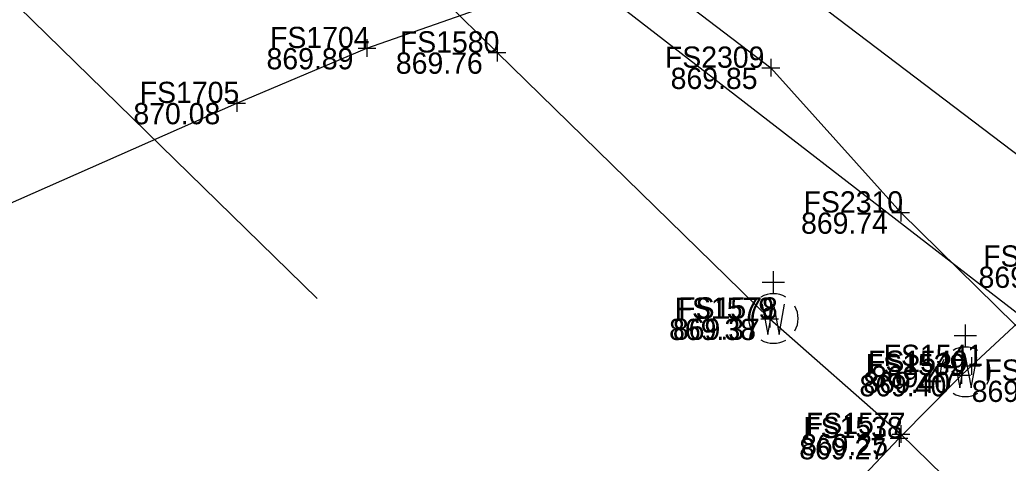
# Model space of a CAD drawing. Extents: x 1479420 to 1479833, y 379731 to 380103.
# Drawn here: x 1479633 to 1479688.8, y 379912.2 to 379937.2 of the extents above; entities that cross this region are included whole.
import ezdxf

# ---------------------------------------------------------------- set-up
doc = ezdxf.new("R2010")
doc.units = 0
for name, color, linetype in [('PM_X_CL_Double_Solid', 7, 'Continuous'), ('PM_X_Crosswalk', 7, 'Continuous'), ('SV_X_Shot_Marker', 7, 'Continuous'), ('SV_X_Text_Elevation', 7, 'Continuous'), ('SV_X_Text_Name', 7, 'Continuous'), ('UT_X_Gas', 7, 'Continuous'), ('UT_X_Sanitary_Line', 7, 'Continuous'), ('UT_X_Water', 7, 'Continuous'), ('UT_X_Water_Cells', 7, 'Continuous')]:
    doc.layers.add(name, color=color, linetype=linetype)

msp = doc.modelspace()

# ---------------------------------------------------------------- linework, layer by layer
at = {"layer": 'PM_X_CL_Double_Solid'}
msp.add_lwpolyline([(1479649.77, 379921.473), (1479632.094, 379938.759), (1479618.381, 379952.22), (1479598.438, 379971.627), (1479578.627, 379990.753), (1479560.467, 380008.345), (1479543.803, 380024.417)], dxfattribs=at)
at = {"layer": 'PM_X_Crosswalk'}
for p, q in [((1479696.985, 379923.758), (1479671.854, 379942.855)), ((1479663.295, 379940.786), (1479694.651, 379916.513))]:
    msp.add_line(p, q, dxfattribs=at)
at = {"layer": 'SV_X_Shot_Marker'}
for p, q in [((1479652.585, 379936.116), (1479652.585, 379935.116)), ((1479652.085, 379935.616), (1479653.085, 379935.616)), ((1479652.585, 379935.616), (1479652.585, 379935.616)), ((1479659.938, 379935.866), (1479659.938, 379934.866)), ((1479659.438, 379935.366), (1479660.438, 379935.366)), ((1479659.938, 379935.366), (1479659.938, 379935.366)), ((1479675.403, 379935.004), (1479675.403, 379934.004)), ((1479674.903, 379934.504), (1479675.903, 379934.504)), ((1479675.403, 379934.504), (1479675.403, 379934.504)), ((1479645.234, 379933.012), (1479645.234, 379932.012)), ((1479644.734, 379932.512), (1479645.734, 379932.512)), ((1479645.234, 379932.512), (1479645.234, 379932.512)), ((1479682.743, 379926.826), (1479682.743, 379925.826)), ((1479682.243, 379926.326), (1479683.243, 379926.326)), ((1479682.743, 379926.326), (1479682.743, 379926.326)), ((1479675.346, 379920.822), (1479675.346, 379919.822)), ((1479674.846, 379920.322), (1479675.846, 379920.322)), ((1479675.346, 379920.322), (1479675.346, 379920.322)), ((1479686.236, 379917.656), (1479687.236, 379917.656)), ((1479686.736, 379918.156), (1479686.736, 379917.156)), ((1479686.736, 379917.656), (1479686.736, 379917.656)), ((1479685.682, 379917.14), (1479686.682, 379917.14)), ((1479686.182, 379917.64), (1479686.182, 379916.64)), ((1479686.182, 379917.14), (1479686.182, 379917.14)), ((1479682.752, 379914.309), (1479682.752, 379913.309)), ((1479682.252, 379913.809), (1479683.252, 379913.809)), ((1479682.649, 379914.082), (1479682.649, 379913.082)), ((1479682.752, 379913.809), (1479682.752, 379913.809)), ((1479682.149, 379913.582), (1479683.149, 379913.582)), ((1479682.649, 379913.582), (1479682.649, 379913.582))]:
    msp.add_line(p, q, dxfattribs=at)
at = {"layer": 'UT_X_Gas'}
msp.add_lwpolyline([(1479667.444, 379946.572), (1479666.862, 379942.802), (1479667.538, 379940.507), (1479675.403, 379934.504), (1479682.743, 379926.326), (1479692.421, 379916.824), (1479702.659, 379906.694), (1479713.881, 379895.567), (1479724.225, 379885.781), (1479733.117, 379877.795), (1479742.697, 379869.326), (1479754.816, 379857.131), (1479762.869, 379849.318), (1479772.436, 379840.641), (1479780.346, 379832.715), (1479784.901, 379828.191), (1479795.906, 379818.324), (1479806.128, 379806.719), (1479816.671, 379794.927)], dxfattribs=at)
at = {"layer": 'UT_X_Sanitary_Line'}
msp.add_lwpolyline([(1479514.622, 379866.87), (1479542.109, 379880.195), (1479565.169, 379891.725), (1479588.442, 379902.577), (1479600.276, 379909.045), (1479620.421, 379921.063), (1479621.963, 379921.485), (1479624.647, 379923.417), (1479645.234, 379932.512), (1479652.585, 379935.616), (1479664.157, 379939.675), (1479679.103, 379944.837), (1479710.112, 379956.448), (1479736.037, 379968.233), (1479798.147, 379991.168), (1479820.4, 379999.933), (1479823.042, 380000.22)], dxfattribs=at)
at = {"layer": 'UT_X_Water'}
for points in [[(1479586.915, 380004.501), (1479604.754, 379987.567), (1479618.613, 379973.926), (1479629.263, 379963.594), (1479633.713, 379960.434), (1479641.035, 379960.303), (1479643.418, 379958.357), (1479650.478, 379950.403), (1479653.168, 379946.48), (1479654.757, 379940.471), (1479659.938, 379935.366), (1479675.346, 379920.322), (1479682.752, 379913.809), (1479688.353, 379908.314)], [(1479653.917, 379883.075), (1479656.453, 379885.901), (1479682.649, 379913.582), (1479686.182, 379917.14), (1479686.736, 379917.656), (1479692.788, 379923.268), (1479699.703, 379929.77), (1479707.876, 379935.91), (1479714.6, 379939.488), (1479720.618, 379942.792), (1479734.686, 379951.003), (1479759.021, 379964.62), (1479771.505, 379971.304), (1479799.27, 379984.838)]]:
    msp.add_lwpolyline(points, dxfattribs=at)
at = {"layer": 'UT_X_Water_Cells'}
for p, q in [((1479675.548, 379921.734), (1479675.548, 379923.006)), ((1479676.183, 379922.371), (1479674.911, 379922.371)), ((1479675.548, 379920.334), (1479675.548, 379920.334)), ((1479686.396, 379918.724), (1479686.396, 379919.995)), ((1479687.031, 379919.36), (1479685.759, 379919.36)), ((1479686.396, 379917.324), (1479686.396, 379917.324))]:
    msp.add_line(p, q, dxfattribs=at)
for points in [[(1479674.911, 379921.154), (1479675.23, 379919.431), (1479675.548, 379921.154), (1479675.868, 379919.431), (1479676.185, 379921.154)], [(1479685.759, 379918.144), (1479686.078, 379916.42), (1479686.396, 379918.144), (1479686.716, 379916.42), (1479687.033, 379918.144)]]:
    msp.add_lwpolyline(points, dxfattribs=at)
for centre, start, end in [((1479675.548, 379920.336), 60.0184, 120.0157), ((1479675.548, 379920.336), 150.0184, 209.9816), ((1479675.548, 379920.336), 330.0184, 29.9816), ((1479675.548, 379920.336), 239.9843, 299.9816), ((1479686.396, 379917.325), 60.0184, 120.0157), ((1479686.396, 379917.325), 150.0184, 209.9816), ((1479686.396, 379917.325), 330.0184, 29.9816), ((1479686.396, 379917.325), 239.9843, 299.9816)]:
    msp.add_arc(centre, 1.4, start, end, dxfattribs=at)

# ---------------------------------------------------------------- texts
at = {"layer": 'SV_X_Text_Elevation'}
for s, p in [('869.89', (1479646.916, 379934.416)), ('869.76', (1479654.222, 379934.166)), ('869.85', (1479669.744, 379933.304)), ('870.08', (1479639.395, 379931.312)), ('869.74', (1479677.112, 379925.126)), ('869.79', (1479687.138, 379922.068)), ('869.38', (1479669.658, 379919.122)), ('869.37', (1479669.87, 379919.134)), ('869.47', (1479681.067, 379916.456)), ('869.40', (1479680.409, 379915.94)), ('869.40', (1479680.623, 379916.124)), ('869.47', (1479686.752, 379915.624)), ('869.25', (1479677.111, 379912.609)), ('869.27', (1479677.008, 379912.382))]:
    msp.add_text(s, height=1.2, dxfattribs=at).set_placement(p)
at = {"layer": 'SV_X_Text_Name'}
for s, p in [('FS1704', (1479647.115, 379935.616)), ('FS1580', (1479654.449, 379935.366)), ('FS2309', (1479669.422, 379934.504)), ('FS1705', (1479639.755, 379932.512)), ('FS2310', (1479677.254, 379926.326)), ('FS1542', (1479687.403, 379923.268)), ('FS1578', (1479670.173, 379920.334)), ('FS1579', (1479669.971, 379920.322)), ('FS1541', (1479681.776, 379917.656)), ('FS1539', (1479680.769, 379917.14)), ('FS1540', (1479680.898, 379917.324)), ('FS2311', (1479687.47, 379916.824)), ('FS1577', (1479677.386, 379913.809)), ('FS1538', (1479677.236, 379913.582))]:
    msp.add_text(s, height=1.2, dxfattribs=at).set_placement(p)

doc.saveas('drawing.dxf')
